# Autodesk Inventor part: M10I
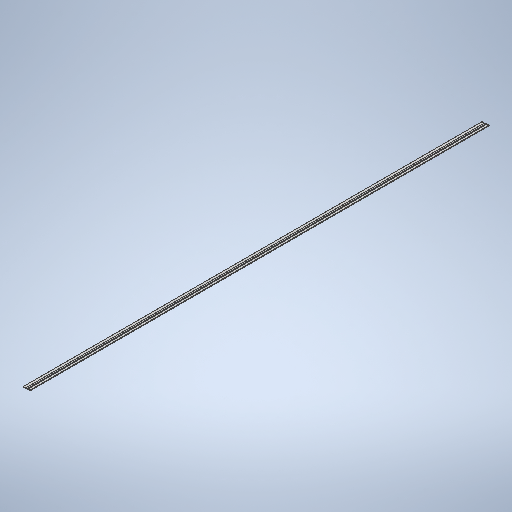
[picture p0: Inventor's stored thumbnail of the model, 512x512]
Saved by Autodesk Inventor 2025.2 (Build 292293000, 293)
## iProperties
Created: 2024-05
Part Number: M10I
Material: Aluminum 6061
Document SubType Name: Modeling
Designer: Olivier St-Arneault
Density: 2.7 g/cm^3
Appearance: Aluminum - Polished
Mass: 3009.29 g
Surface Area: 43731.8 cm^2
Volume: 1114.55 cm^3
Author: Olivier St-Arneault
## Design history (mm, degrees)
sketch "Sketch1"
  geometry: L1 (29.659, 0.508)-(42.359, 0.508); L2 (42.359, 0.508)-(42.359, 25.4); L3 (42.359, 25.4)-(-33.841, 25.4); L4 (-33.841, 25.4)-(-33.841, 0.508); L5 (-33.841, 0.508)-(-79.879, 0.508); L6 (-79.879, 0.508)-(-79.879, 25.4); L7 (-79.879, 25.4)-(-156.079, 25.4); L8 (-156.079, 25.4)-(-156.079, 0.508); L9 (-156.079, 0.508)-(-202.116, 0.508); L10 (-202.116, 0.508)-(-202.116, 25.4); L11 (-202.116, 25.4)-(-278.316, 25.4); L12 (-278.316, 25.4)-(-278.316, 0.508); L13 (-278.316, 0.508)-(-337.054, 0.508); L14 (-337.054, 1.524)-(-322.703, 1.524); L15 (-322.703, 3.556)-(-340.737, 3.556); L16 (-340.737, 3.556)-(-353.066, 0.508); L17 (-353.066, 0.508)-(-368.941, 0.508); L18 (-368.941, 0)-(-353.004, 0); L19 (-353.004, 0)-(-340.675, 3.048); L20 (-340.675, 3.048)-(-322.703, 3.048); L21 (-322.703, 2.032)-(-337.054, 2.032); L22 (-337.054, 0)-(-277.808, 0); L23 (-277.808, 0)-(-277.808, 24.892); L24 (-277.808, 24.892)-(-202.624, 24.892); L25 (-202.624, 24.892)-(-202.624, 0); L26 (-202.624, 0)-(-155.571, 0); L27 (-155.571, 0)-(-155.571, 24.892); L28 (-155.571, 24.892)-(-80.387, 24.892); L29 (-80.387, 24.892)-(-80.387, 0); L30 (-80.387, 0)-(-33.333, 0); L31 (-33.333, 0)-(-33.333, 24.892); L32 (-33.333, 24.892)-(41.851, 24.892); L33 (41.851, 24.892)-(41.851, 1.016); L34 (41.851, 1.016)-(29.659, 1.016); L35 (-368.941, 0.508)-(-368.941, 0); L36 (29.659, 1.016)-(29.659, 0.508); L37 (-887.45, 0)-(197.327, 0) reference; L38 (29.659, 1.016)-(26.825, 2.337); L39 (26.825, 2.337)-(26.611, 1.877); L40 (26.611, 1.877)-(29.659, 0.508); L41 (-566.166, 24.888)-(-566.166, -0.004); L42 (-641.35, 24.888)-(-566.166, 24.888); L43 (-565.658, 0.504)-(-565.658, 25.396); L44 (-565.658, 25.396)-(-641.858, 25.396); L45 (-566.166, -0.004)-(-519.112, -0.004); L46 (-519.62, 25.396)-(-519.62, 0.504); L47 (-519.112, -0.004)-(-519.112, 24.888); L48 (-519.112, 24.888)-(-443.928, 24.888); L49 (-443.42, 25.396)-(-519.62, 25.396); L50 (-519.62, 0.504)-(-565.658, 0.504); L51 (-443.42, 0.504)-(-443.42, 25.396); L52 (-397.383, 0.504)-(-443.42, 0.504); L53 (-397.383, 25.396)-(-397.383, 0.504); L54 (-333.883, 0.504)-(-321.183, 0.504); L55 (-321.183, 0.504)-(-321.183, 25.396); L56 (-321.183, 25.396)-(-397.383, 25.396); L57 (-641.35, -0.004)-(-641.35, 24.888); L58 (-641.858, 25.396)-(-641.858, 0.504); L59 (-700.595, -0.004)-(-641.35, -0.004); L60 (-700.595, 1.52)-(-684.212, 1.52); L61 (-684.212, 3.552)-(-704.278, 3.552); L62 (-704.278, 3.552)-(-716.607, 0.504); L63 (-641.858, 0.504)-(-700.595, 0.504); L64 (-443.928, 24.888)-(-443.928, -0.004)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; A1 r 0.508 centre (-337.054, 1.016) between (-337.054, 1.524) and (-337.054, 0.508); A2 r 1.016 centre (-322.703, 2.54) between (-322.703, 1.524) and (-322.703, 3.556); A3 r 0.508 centre (-322.703, 2.54) between (-322.703, 2.032) and (-322.703, 3.048); A4 r 1.016 centre (-337.054, 1.016) between (-337.054, 2.032) and (-337.054, 0); A5 r 1.016 centre (-684.212, 2.536) between (-684.212, 1.52) and (-684.212, 3.552); A6 r 0.508 centre (-684.212, 2.536) between (-684.212, 2.028) and (-684.212, 3.044); A7 r 0.508 centre (-700.595, 1.012) between (-700.595, 1.52) and (-700.595, 0.504); A8 r 1.016 centre (-700.595, 1.012) between (-700.595, 2.028) and (-700.595, -0.004); 6 further points
  constraints: 158 end point, 36 perpendicular, 20 point on circle, 10 horizontal, 10 point on line, 8 centre point, 8 tangent, 5 collinear, 4 parallel, 2 vertical, 36 other
  dimensions: "d0" = 12.7 distance of L1.start L1.end; "d1" = 24.892 distance of L1.end L2.end; "d2" = 76.2 distance of L2.end L3.end; "d3" = 24.892 distance of L3.end L4.end; "d5" = 46.0375 distance of L4.end L5.end; "d6" = 24.892 distance of L5.end L6.end; "d7" = 76.2 distance of L6.end L7.end; "d8" = 46.0375 distance of L8.end L9.end (= d5); "d9" = 76.2 distance of L10.end L11.end; "d11" = 59.2455 horizontal distance of L12.end point (-337.562, 1.016); "d12" = 15.875 horizontal distance of point (-321.687, 2.54) point (-337.562, 1.016); "d13" = 19.05 horizontal distance of L15.end point (-321.687, 2.54); "d14" = 12.7 distance of L15.end L16.end; "d16" = 15.875 distance of L16.end L17.end; "d17" = 0.508 distance between parallel lines of L16 L19; "d18" = 1.016 distance between parallel lines of L13 L14; "d19" = 1.016 distance between parallel lines of L20 L21; "d24" = 0.508 distance of L38.end L39.end; "d25" = 15.24 distance from line of L33 L39.end; "d26" = 155 deg angle of L34 L38; "d27" = 12.7 distance of L54.start L54.end; "d28" = 24.892 distance of L54.end L55.end; "d29" = 76.2 distance of L55.end L53.start; "d30" = 24.892 distance of L53.start L52.start; "d31" = 46.0375 distance of L52.start L51.start; "d32" = 24.892 distance of L51.start L49.start; "d33" = 76.2 distance of L49.start L46.start; "d34" = 46.0375 distance of L46.end L43.start (= d31); "d35" = 76.2 distance of L43.end L44.end; "d36" = 59.2455 horizontal distance of L58.end point (-701.103, 1.012); "d37" = 15.875 horizontal distance of point (-685.228, 2.536) point (-701.103, 1.012); "d38" = 19.05 horizontal distance of L61.end point (-685.228, 2.536); "d39" = 12.7 distance of L61.end L62.end; "d40" = 15.875 distance of L62.end L77.end; "d41" = 0.508 distance between parallel lines of L62 L76; "d42" = 1.016 distance between parallel lines of L63 L60; "d43" = 1.016 distance between parallel lines of L75 L74; "d44" = 0.508 distance of L67.start L67.end; "d45" = 15.24 distance from line of L71 L67.end; "d46" = 155 deg angle of L72 L69; "d47" = 42.86613 distance between parallel lines of L12 L55
extrude "Extrusion1" new body sketch "Sketch1" distance "d20" = 3048; taper "d21" = 0 deg
fillet "Fillet1" dims "d22" = 0.508
sketch "Esquisse2"
  geometry: L1 (3.683, 3048)-(3.683, 0) reference; L2 (3.683, 0)-(62.421, 0) reference; L3 (18.923, 0)-(18.923, 3048); L4 (62.421, 3048)-(62.421, 0) reference; L5 (61.913, 3048)-(3.683, 3048) reference; 1 further point
  constraints: 2 end point, 2 point on line, 1 parallel
  dimensions: "d48" = 15.24 distance between parallel lines of L3 L1
extrude "Extrusion2" cut sketch "Esquisse2" extent not by distance; stored distance "d50" = 25.4; taper "d51" = 0 deg
body "Solid1"
other parameters: "d54" = 25.4
